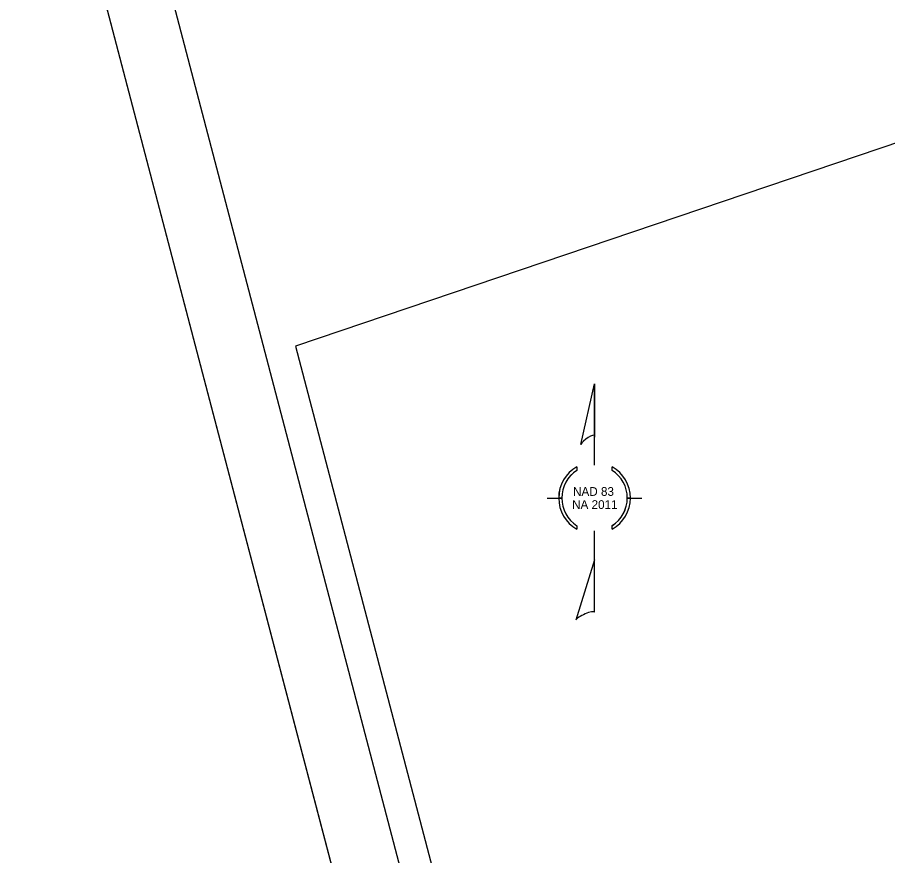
# Model space of a CAD drawing. Extents: x 1366699 to 1368206, y 878140 to 880064.
# Drawn here: x 1366710.8 to 1367208.6, y 879104.5 to 879584.2 of the extents above; entities that cross this region are included whole.
import ezdxf

# ---------------------------------------------------------------- set-up
doc = ezdxf.new("R2010")
doc.units = 0
for name, color, linetype in [('Prop Shade Medium', 7, 'Continuous'), ('Sheet_Plot_Border_Outside_CELL', 7, 'Continuous'), ('Sheet_Title_Block_Text', 7, 'Continuous'), ('Typical Terminator CELL', 7, 'Continuous'), ('z - Construction', 7, 'Continuous')]:
    doc.layers.add(name, color=color, linetype=linetype)

msp = doc.modelspace()

# ---------------------------------------------------------------- linework, layer by layer
at = {"layer": 'Prop Shade Medium'}
msp.add_line((1366756.62, 879758.15), (1367168.57, 878186.24), dxfattribs=at)
at = {"layer": 'Sheet_Plot_Border_Outside_CELL'}
msp.add_lwpolyline([(1366869.99, 879396.08), (1367149.56, 878329.29), (1367149.56, 878329.29), (1368092.87, 878576.5), (1368092.87, 878576.5), (1367795.92, 879709.62)], close=True, dxfattribs=at)
at = {"layer": 'Sheet_Title_Block_Text'}
msp.add_line((1367141.8, 878140.46), (1366710.84, 879784.92), dxfattribs=at)
at = {"layer": 'Typical Terminator CELL'}
msp.add_lwpolyline([(1367141.8, 878140.46), (1366710.84, 879784.92), (1367774.9, 880063.78), (1368205.86, 878419.32)], close=True, dxfattribs=at)
at = {"layer": 'z - Construction'}
for p, q in [((1367033.05, 879339.72), (1367040.93, 879374.49)), ((1367040.96, 879374.49), (1367040.93, 879374.49)), ((1367040.96, 879374.49), (1367040.93, 879374.49)), ((1367040.96, 879374.49), (1367040.96, 879344.02)), ((1367040.96, 879327.89), (1367040.96, 879374.49)), ((1367040.96, 879344.02), (1367040.96, 879344.88)), ((1367040.96, 879344.88), (1367040.97, 879344.87)), ((1367030.88, 879327.01), (1367030.89, 879326.99)), ((1367030.89, 879326.99), (1367030.89, 879324.95)), ((1367051.06, 879324.93), (1367051.06, 879326.98)), ((1367013.96, 879309.13), (1367022.21, 879309.14)), ((1367022.21, 879309.14), (1367020.46, 879309.14)), ((1367020.46, 879309.14), (1367022.21, 879309.14)), ((1367059.71, 879309.14), (1367067.96, 879309.14)), ((1367059.71, 879309.14), (1367061.46, 879309.14)), ((1367061.47, 879309.14), (1367059.71, 879309.14)), ((1367030.89, 879293.32), (1367030.89, 879291.28)), ((1367051.07, 879291.3), (1367051.07, 879293.34)), ((1367051.07, 879291.28), (1367051.07, 879291.3)), ((1367040.97, 879243.79), (1367040.97, 879290.39)), ((1367040.95, 879273.78), (1367030.19, 879239.32)), ((1367040.98, 879243.79), (1367040.95, 879273.78))]:
    msp.add_line(p, q, dxfattribs=at)
for radius, start, end in [(20.5, 119.4397, 240.5714), (20.5, 299.5259, 60.4851), (20.5, 0.0055, 60.4851), (18.75, 122.5087, 237.5024), (18.75, 302.6061, 57.4049), (18.75, 0.0055, 57.4049), (20.5, 180.0055, 240.5714), (18.75, 180.0055, 237.5024)]:
    msp.add_arc((1367040.96, 879309.14), radius, start, end, dxfattribs=at)
for centre, major_axis, ratio, start_param, end_param in [((1367036.94, 879341.88), (3.99, 3.06), 0.261723, 6.225794, 8.917625), ((1367040.96, 879309.14), (0, 20.53), 0.998737, 0.514018, 1.570796), ((1367040.96, 879309.14), (0, 18.77), 0.998737, 0.567287, 1.570796), ((1367040.96, 879309.14), (0, 18.77), 0.998737, 3.71058, 4.712389), ((1367040.96, 879309.14), (0, 20.53), 0.998737, 3.657116, 4.712389), ((1367035.58, 879241.36), (5.39, 2.43), 0.225493, 6.280036, 9.220301)]:
    msp.add_ellipse(centre, major_axis=major_axis, ratio=ratio, start_param=start_param, end_param=end_param, dxfattribs=at)

# ---------------------------------------------------------------- texts
for s, p in [('NAD 83', (1367028.66, 879310.39)), ('NA 2011', (1367028.12, 879302.89))]:
    msp.add_text(s, height=5, rotation=0.0055, dxfattribs=at).set_placement(p)

doc.saveas('drawing.dxf')
